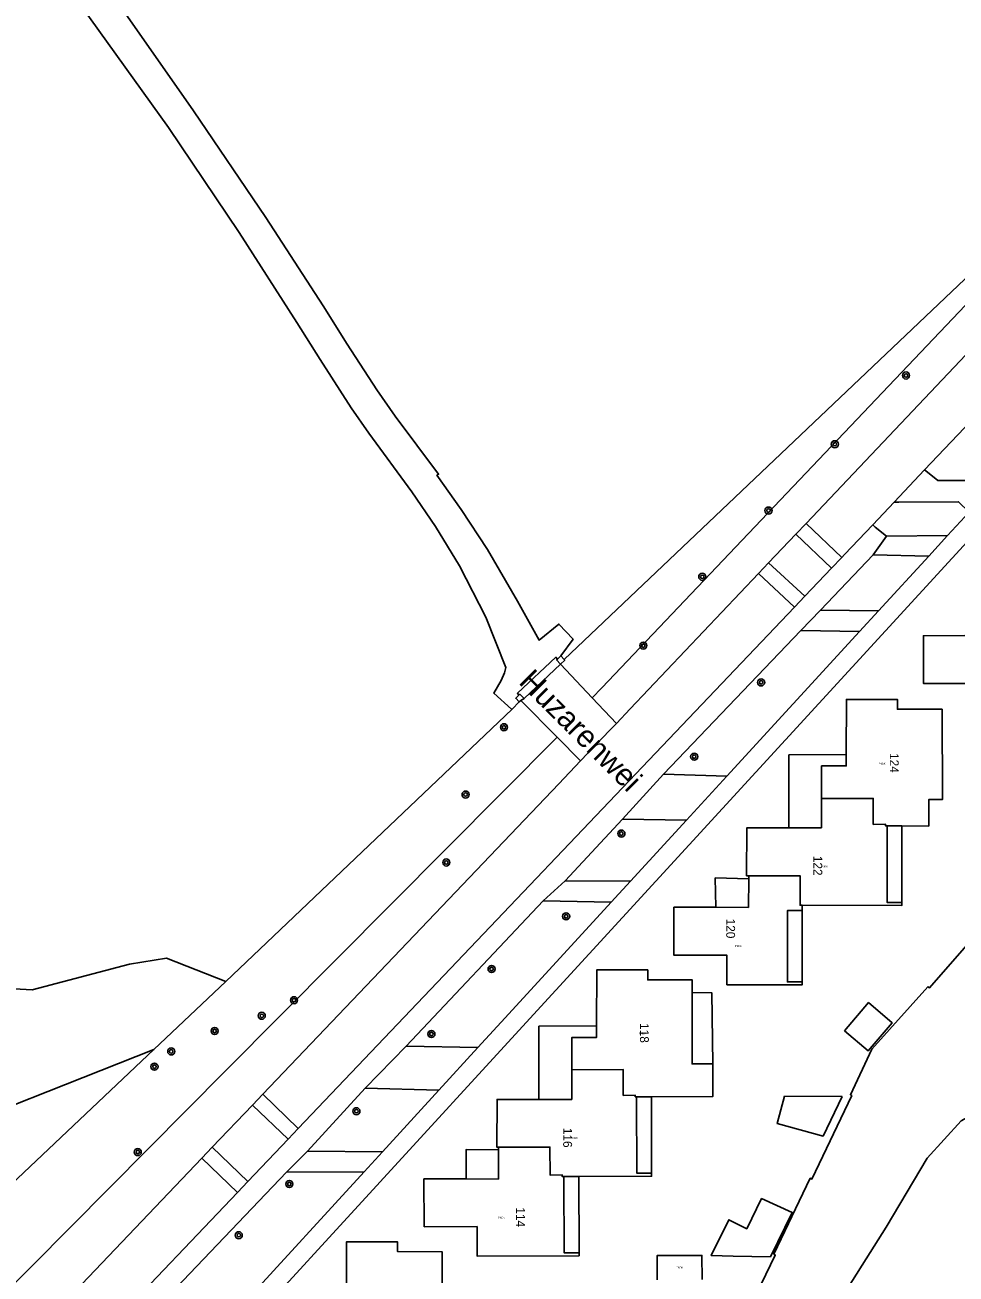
# Model space of a CAD drawing. Extents: x 132994 to 136000, y 393499 to 395512.
# Drawn here: x 133162.3 to 133267.6, y 393903.8 to 394045 of the extents above; entities that cross this region are included whole.
import ezdxf

# ---------------------------------------------------------------- set-up
doc = ezdxf.new("R2010")
doc.units = 0
for name, color, linetype in [('gg-anno-huisnummerreeks BGT', 7, 'Continuous'), ('gg-anno-openbare ruimte label', 7, 'Continuous'), ('gg-bbg-overig bouwwerk', 7, 'Continuous'), ('gg-knt-bronhoudergrens niveau 01', 7, 'Continuous'), ('gg-kwrk-kunstwerk niveau 01', 7, 'Continuous'), ('gt-symb-boom', 7, 'Continuous'), ('gx-grn-IMGEO niveau 01', 7, 'Continuous'), ('gx-grn-maaiveld', 7, 'Continuous'), ('kenmerkpunt-x pandkandidaat', 7, 'Continuous')]:
    doc.layers.add(name, color=color, linetype=linetype)

# ---------------------------------------------------------------- blocks, each defined once
blk = doc.blocks.new('gt0-BOOM')
at = {"layer": 'gt-symb-boom'}
for radius in [0.4, 0.2]:
    blk.add_circle((0, 0), radius, dxfattribs=at)

msp = doc.modelspace()

# ---------------------------------------------------------------- linework, layer by layer
at = {"layer": 'gg-bbg-overig bouwwerk'}
msp.add_lwpolyline([(133254.71, 393923.89), (133248.21, 393923.93), (133247.36, 393920.85), (133252.57, 393919.42), (133254.71, 393923.89)], dxfattribs=at)
at = {"layer": 'gg-knt-bronhoudergrens niveau 01'}
msp.add_lwpolyline([(133242.41, 393905.86), (133239.91, 393905.92), (133241.89, 393909.96), (133243.93, 393908.96), (133245.6, 393912.36), (133249.07, 393910.79), (133246.61, 393905.77), (133242.41, 393905.86)], dxfattribs=at)
at = {"layer": 'gg-kwrk-kunstwerk niveau 01'}
for p, q in [((133252.4, 393954.27), (133252.4, 393957.59)), ((133261.48, 393954.49), (133259.81, 393954.49)), ((133259.81, 393954.49), (133259.81, 393954.26)), ((133261.48, 393954.49), (133261.47, 393945.84)), ((133244.14, 393945.29), (133244.15, 393948.51)), ((133244.14, 393945.29), (133240.43, 393945.3)), ((133250.2, 393936.86), (133250.21, 393944.93)), ((133224.16, 393926.9), (133224.16, 393923.56)), ((133224.16, 393923.56), (133220.44, 393923.57)), ((133231.48, 393923.88), (133231.48, 393923.59)), ((133233.18, 393923.88), (133231.48, 393923.88)), ((133233.17, 393915.22), (133233.18, 393923.88)), ((133215.87, 393917.88), (133215.87, 393914.57)), ((133215.87, 393914.57), (133212.21, 393914.58)), ((133224.93, 393914.86), (133223.25, 393914.85)), ((133223.25, 393914.85), (133223.25, 393914.61)), ((133224.97, 393906.22), (133224.93, 393914.86))]:
    msp.add_line(p, q, dxfattribs=at)
for points in [[(133255.19, 393962.57), (133248.69, 393962.52), (133248.7, 393954.27)], [(133252.4, 393957.59), (133252.4, 393961.28), (133255.19, 393961.28), (133255.19, 393962.57)], [(133252.4, 393954.27), (133252.4, 393954.27), (133248.7, 393954.27)], [(133259.81, 393954.26), (133259.79, 393945.84), (133261.47, 393945.84)], [(133240.43, 393945.3), (133240.37, 393948.61), (133244.15, 393948.51)], [(133250.2, 393936.86), (133248.52, 393936.86), (133248.53, 393944.93), (133250.21, 393944.93)], [(133240.09, 393927.59), (133237.75, 393927.58), (133237.77, 393935.65)], [(133240.09, 393927.59), (133239.98, 393935.64), (133237.77, 393935.65)], [(133226.96, 393931.9), (133220.43, 393931.85), (133220.44, 393923.57)], [(133224.16, 393926.9), (133224.17, 393930.58), (133226.96, 393930.58), (133226.96, 393931.9)], [(133233.17, 393915.22), (133231.52, 393915.22), (133231.48, 393923.59)], [(133215.87, 393917.88), (133212.2, 393917.91), (133212.21, 393914.58)], [(133224.97, 393906.22), (133223.29, 393906.21), (133223.25, 393914.61)]]:
    msp.add_lwpolyline(points, dxfattribs=at)
at = {"layer": 'gx-grn-IMGEO niveau 01'}
msp.add_lwpolyline([(133254.98, 393931.34), (133257.65, 393929.05), (133260.38, 393932.22), (133257.71, 393934.52), (133254.98, 393931.34)], dxfattribs=at)
at = {"layer": 'gx-grn-maaiveld'}
for p, q in [((133280.48, 394027.62), (133223.28, 393973.31)), ((133276.01, 394007.38), (133264.04, 393994.74)), ((133264.04, 393994.74), (133260.6, 393991.11)), ((133264.04, 393994.74), (133264.35, 393994.49)), ((133260.6, 393991.11), (133258.17, 393988.54)), ((133261.14, 393991.11), (133260.6, 393991.11)), ((133269.06, 393989.97), (133266.64, 393987.33)), ((133249.48, 393987.48), (133250.63, 393988.69)), ((133250.63, 393988.69), (133254.68, 393984.85)), ((133258.17, 393988.54), (133258.45, 393988.28)), ((133246.4, 393984.23), (133249.48, 393987.48)), ((133253.52, 393983.63), (133249.48, 393987.48)), ((133259.74, 393987.26), (133258.22, 393985.14)), ((133258.45, 393988.28), (133259.74, 393987.26)), ((133259.74, 393987.26), (133266.64, 393987.33)), ((133266.64, 393987.33), (133264.5, 393985)), ((133258.22, 393985.14), (133252.28, 393978.9)), ((133254.68, 393984.85), (133253.52, 393983.63)), ((133264.5, 393985), (133258.22, 393985.14)), ((133264.5, 393985), (133258.83, 393978.82)), ((133245.25, 393983.02), (133246.4, 393984.23)), ((133249.32, 393979.22), (133245.25, 393983.02)), ((133250.49, 393980.46), (133246.4, 393984.23)), ((133253.52, 393983.63), (133250.49, 393980.46)), ((133250.49, 393980.46), (133249.32, 393979.22)), ((133249.32, 393979.22), (133193.23, 393920.29)), ((133250.06, 393976.6), (133252.28, 393978.9)), ((133258.83, 393978.82), (133252.28, 393978.9)), ((133258.83, 393978.82), (133256.68, 393976.47)), ((133250.06, 393976.6), (133234.5, 393960.33)), ((133256.68, 393976.47), (133241.68, 393960.12)), ((133256.68, 393976.47), (133250.06, 393976.6)), ((133222.52, 393973.35), (133222.9, 393973.71)), ((133222.9, 393973.71), (133223.28, 393973.31)), ((133218.75, 393968.9), (133222.89, 393972.77)), ((133222.89, 393972.77), (133226.47, 393968.97)), ((133218.4, 393968.66), (133218.75, 393968.9)), ((133226.47, 393968.97), (133229.2, 393966.09)), ((133217.39, 393967.68), (133185.02, 393936.92)), ((133218.4, 393968.66), (133218.19, 393968.51)), ((133222.49, 393964.54), (133218.4, 393968.66)), ((133222.49, 393964.54), (133225.15, 393961.85)), ((133234.5, 393960.33), (133229.87, 393955.25)), ((133241.68, 393960.12), (133234.5, 393960.33)), ((133241.68, 393960.12), (133237.12, 393955.16)), ((133223.4, 393948.27), (133229.87, 393955.25)), ((133237.12, 393955.16), (133229.87, 393955.25)), ((133237.12, 393955.16), (133230.8, 393948.26)), ((133252.4, 393954.27), (133248.7, 393954.27)), ((133220.93, 393946.01), (133223.4, 393948.27)), ((133230.8, 393948.26), (133223.4, 393948.27)), ((133230.8, 393948.26), (133228.61, 393945.87)), ((133244.15, 393948.51), (133244.15, 393948.86)), ((133205.42, 393929.6), (133220.93, 393946.01)), ((133228.61, 393945.87), (133220.93, 393946.01)), ((133250.21, 393945.53), (133250.21, 393945.28)), ((133250.21, 393944.93), (133250.21, 393945.28)), ((133185.02, 393936.92), (133176.91, 393929.22)), ((133205.42, 393929.6), (133200.78, 393924.83)), ((133213.54, 393929.44), (133205.42, 393929.6)), ((133213.54, 393929.44), (133209.12, 393924.61)), ((133188.05, 393922.93), (133189.21, 393924.15)), ((133193.23, 393920.29), (133189.21, 393924.15)), ((133194.27, 393917.71), (133200.78, 393924.83)), ((133200.78, 393924.83), (133209.12, 393924.61)), ((133202.74, 393917.66), (133209.12, 393924.61)), ((133183.49, 393918.16), (133188.05, 393922.93)), ((133192.08, 393919.08), (133188.05, 393922.93)), ((133193.23, 393920.29), (133192.08, 393919.08)), ((133182.31, 393916.92), (133183.49, 393918.16)), ((133187.53, 393914.3), (133183.49, 393918.16)), ((133192.08, 393919.08), (133187.53, 393914.3)), ((133215.87, 393917.88), (133215.87, 393918.16)), ((133186.36, 393913.06), (133182.31, 393916.92)), ((133194.27, 393917.71), (133191.89, 393915.36)), ((133202.74, 393917.66), (133194.27, 393917.71)), ((133202.74, 393917.66), (133200.67, 393915.4)), ((133191.89, 393915.36), (133176.25, 393898.96)), ((133200.67, 393915.4), (133185.57, 393898.91)), ((133191.89, 393915.36), (133200.67, 393915.4)), ((133186.36, 393913.06), (133187.53, 393914.3))]:
    msp.add_line(p, q, dxfattribs=at)
for points in [[(133217.39, 393967.68), (133217.35, 393967.71), (133215.32, 393969.5), (133216.17, 393970.93), (133216.54, 393971.79), (133216.7, 393972.4), (133214.42, 393978.09), (133211.46, 393983.9), (133208.75, 393988.35), (133206.08, 393992.26), (133201.19, 393998.9), (133199.19, 394001.77), (133195.69, 394007.21), (133193.05, 394011.42), (133186.53, 394021.59), (133178.55, 394033.45), (133167.69, 394048.61), (133153.53, 394068.47)], [(133160.27, 394066.11), (133165.34, 394058.45), (133170.74, 394050.56), (133181.38, 394035.34), (133189.56, 394023.3), (133196.05, 394013.29), (133198.74, 394008.96), (133202.09, 394003.81), (133204.17, 394000.82), (133209.09, 393994.25), (133208.9, 393994.15), (133211.66, 393990.26), (133214.63, 393985.75), (133218.02, 393979.89), (133220.46, 393975.5), (133222.7, 393977.32), (133224.29, 393975.59), (133222.9, 393973.71)], [(133250.63, 393988.69), (133291.47, 394031.81), (133294.54, 394034.96), (133307.69, 394048.84), (133308.29, 394049.56), (133308.84, 394050.33), (133309.32, 394051.14), (133309.73, 394051.99), (133310.08, 394052.87), (133310.35, 394053.78), (133310.55, 394054.7), (133310.67, 394055.64), (133310.72, 394056.59), (133310.69, 394057.53), (133310.61, 394058.48), (133310.46, 394059.42), (133310.23, 394060.34), (133309.93, 394061.24), (133309.56, 394062.12), (133309.12, 394062.95), (133308.77, 394063.51)], [(133283.53, 394028.99), (133282.36, 394027.75), (133227.54, 393970.1), (133226.47, 393968.97)], [(133303.47, 394024.43), (133274.71, 393992.99), (133218.58, 393931.8), (133186.41, 393896.69), (133166.62, 393875.06)], [(133264.35, 393994.49), (133265.55, 393993.53), (133272.32, 393993.53)], [(133261.14, 393991.11), (133267.89, 393991.15), (133269.06, 393989.97)], [(133258.17, 393988.54), (133254.98, 393985.17), (133254.68, 393984.85)], [(133229.2, 393966.09), (133230.76, 393967.73), (133245.25, 393983.02)], [(133268.6, 393976.01), (133263.9, 393975.99), (133263.92, 393970.59), (133269.92, 393970.61), (133269.93, 393967.25), (133278.46, 393967.28), (133278.46, 393967.61)], [(133222.52, 393973.35), (133222.35, 393973.57), (133218.01, 393969.5), (133218.17, 393969.27)], [(133222.52, 393973.35), (133222.43, 393973.27), (133222.89, 393972.77)], [(133222.89, 393972.77), (133223.36, 393973.22), (133223.28, 393973.31)], [(133218.19, 393968.51), (133217.81, 393968.93), (133218.17, 393969.27)], [(133218.17, 393969.27), (133218.29, 393969.38), (133218.75, 393968.9)], [(133255.19, 393962.57), (133255.2, 393968.8), (133260.96, 393968.79), (133260.97, 393967.68), (133266.01, 393967.68), (133266.05, 393957.47), (133264.5, 393957.47), (133264.51, 393954.48), (133261.48, 393954.49)], [(133218.19, 393968.51), (133217.4, 393967.68), (133217.39, 393967.68)], [(133229.2, 393966.09), (133228.45, 393965.31), (133225.15, 393961.85)], [(133222.49, 393964.54), (133185.01, 393926.82), (133158.68, 393900.33), (133158.26, 393899.9), (133140.03, 393881.55), (133139.51, 393881.09)], [(133189.21, 393924.15), (133222.67, 393959.24), (133225.15, 393961.85)], [(133252.4, 393957.59), (133258.23, 393957.6), (133258.24, 393954.67), (133259.62, 393954.68), (133259.62, 393954.49), (133259.81, 393954.49)], [(133248.7, 393954.27), (133243.94, 393954.27), (133243.92, 393948.86), (133244.15, 393948.86)], [(133244.15, 393948.86), (133249.96, 393948.86), (133249.96, 393945.53), (133250.21, 393945.53)], [(133213.54, 393929.44), (133217.02, 393933.24), (133228.61, 393945.87)], [(133240.43, 393945.3), (133235.7, 393945.3), (133235.69, 393939.88), (133241.69, 393939.87), (133241.69, 393936.54), (133250.2, 393936.53), (133250.2, 393936.86)], [(133261.47, 393945.84), (133261.47, 393945.51), (133250.21, 393945.53)], [(133270.08, 393942.5), (133264.58, 393936.18), (133264.42, 393936.32), (133258.08, 393929.25), (133255.65, 393924.11), (133255.8, 393924.01), (133251.3, 393914.57), (133251.11, 393914.66), (133246.98, 393906.09), (133247.15, 393905.98), (133240.78, 393892.79), (133240.59, 393892.88), (133236.53, 393884.38), (133236.7, 393884.26), (133236.68, 393884.23), (133232.25, 393875.15), (133232.04, 393875.16)], [(133185.02, 393936.92), (133178.32, 393939.54), (133174.13, 393938.88), (133163.14, 393935.95), (133157.07, 393936.31)], [(133237.77, 393935.65), (133237.77, 393937.08), (133232.73, 393937.09), (133232.73, 393938.21), (133226.97, 393938.22), (133226.96, 393931.9)], [(133176.91, 393929.22), (133149.07, 393918.22), (133114.24, 393904.97), (133111.45, 393902.35), (133110.07, 393898.61), (133109.9, 393893.39), (133112.9, 393885.76), (133112.97, 393880.83)], [(133176.91, 393929.22), (133176.89, 393929.2), (133118.04, 393873.55), (133112.97, 393880.83)], [(133408.22, 393895.16), (133378.39, 393882.67), (133348.3, 393870.23), (133304.64, 393853.17), (133245.14, 393829.46), (133232.46, 393826.28), (133230.9, 393834.98), (133230.71, 393843.16), (133231.27, 393849.91), (133232.68, 393856.6), (133235.96, 393866.1), (133247.23, 393886.87), (133253.64, 393899.52), (133259.69, 393909.13), (133264.33, 393916.95), (133268.16, 393921.15), (133283.65, 393929.71)], [(133224.16, 393926.9), (133229.94, 393926.96), (133229.96, 393924.03), (133231.32, 393924.05), (133231.32, 393923.87), (133231.48, 393923.88)], [(133233.18, 393923.88), (133240.1, 393923.91), (133240.09, 393927.59)], [(133220.44, 393923.57), (133215.7, 393923.57), (133215.69, 393918.16), (133215.87, 393918.16)], [(133215.87, 393918.16), (133221.68, 393918.18), (133221.69, 393915.02), (133223.07, 393915.03), (133223.07, 393914.85), (133223.25, 393914.85)], [(133144.18, 393876.68), (133146.77, 393879.41), (133148.35, 393881.3), (133182.31, 393916.92)], [(133233.17, 393915.22), (133233.17, 393914.89), (133224.93, 393914.86)], [(133224.97, 393906.22), (133224.97, 393905.89), (133213.46, 393905.84), (133213.45, 393909.2), (133207.46, 393909.17), (133207.44, 393914.59), (133212.21, 393914.58)], [(133186.36, 393913.06), (133171.99, 393897.96), (133148.3, 393873.07)], [(133205.04, 393893.1), (133207.98, 393893.11), (133207.96, 393896.2), (133209.53, 393896.2), (133209.49, 393906.36), (133204.45, 393906.37), (133204.44, 393907.48), (133198.68, 393907.48), (133198.67, 393901.31)], [(133233.81, 393903.19), (133233.8, 393905.91), (133238.87, 393905.93), (133238.88, 393903.21)]]:
    msp.add_lwpolyline(points, dxfattribs=at)

# ---------------------------------------------------------------- block references
at = {"layer": 'gt-symb-boom'}
for p in [(133261.94, 394005.42), (133253.89, 393997.65), (133246.39, 393990.15), (133238.9, 393982.66), (133232.24, 393974.88), (133245.56, 393970.72), (133216.48, 393965.65), (133237.99, 393962.32), (133212.14, 393958.04), (133229.76, 393953.63), (133209.96, 393950.36), (133223.51, 393944.27), (133215.08, 393938.32), (133192.75, 393934.79), (133189.1, 393933.03), (133183.77, 393931.31), (133208.28, 393930.97), (133178.86, 393929), (133176.97, 393927.28), (133199.8, 393922.24), (133175.08, 393917.62), (133192.21, 393914.01), (133186.5, 393908.22)]:
    msp.add_blockref('gt0-BOOM', p, dxfattribs=at)

# ---------------------------------------------------------------- texts
at = {"layer": 'gg-anno-huisnummerreeks BGT'}
for s, p in [('124', (133260.11, 393962.73)), ('122', (133251.47, 393951.11)), ('120', (133241.61, 393944.01)), ('118', (133231.86, 393932.2)), ('116', (133223.18, 393920.36)), ('114', (133217.86, 393911.37))]:
    msp.add_text(s, height=1, rotation=270, dxfattribs=at).set_placement(p)
at = {"layer": 'gg-anno-openbare ruimte label'}
msp.add_text('Huzarenwei', height=2.5, rotation=315, dxfattribs=at).set_placement((133218.05, 393970.66))
at = {"layer": 'kenmerkpunt-x pandkandidaat'}
for p in [(133258.85, 393961.43), (133252.33, 393949.8), (133242.58, 393940.82), (133231.76, 393930.94), (133224.06, 393919.11), (133215.83, 393910.11), (133235.97, 393904.46)]:
    msp.add_text('PNDK', height=0.2, dxfattribs=at).set_placement(p)

doc.saveas('drawing.dxf')
